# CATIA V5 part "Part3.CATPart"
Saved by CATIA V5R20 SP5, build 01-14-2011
Part number: Part3
Material "DS Light Blue": density 7860 kg/m3, Young's modulus 2e+11 Pa, Poisson ratio 0.266
Bounding box of the stored display mesh (mm): x -36.885 to 36.885, y -32.342 to 32.342, z -80 to 0
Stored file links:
  D:\zhonggao\Part3.CATPart
  C:\Program Files\Dassault Systemes\B20\intel_a\startup\materials\Catalog.CATMaterial
  C:\Program Files\Dassault Systemes\B20\intel_a\startup\materials\blue_env_512x512.jpg
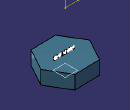
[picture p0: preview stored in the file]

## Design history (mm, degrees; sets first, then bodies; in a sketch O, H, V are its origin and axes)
Body1 (main body), material "DS Light Blue"
  DatumSurface1
  DatumSurface2
  Sketch1 on zx-plane, origin (0, 0, 0), H (-1, 0, 0), V (0, 0, 1)
    polyline C1
    polyline C2
    polyline C3
    polyline C4
    polyline C5
    polyline C6
    polyline C7
    polyline C8
    polyline C9
    polyline C10
    polyline C11
    polyline C12
    polyline C13
    polyline C14
    polyline C15
    polyline C16
    polyline C17
    polyline C18
    polyline C19
    polyline C20
    polyline C21
    polyline C22
    polyline C23
    polyline C24
    polyline C25
  DatumSurface3
  Plane1: type Offset, RefPlane DatumSurface3, Offset 20, reversed
  Sketch2 on Plane1, origin (0, 0, -80), H (1, 0, 0), V (0, 1, 0)
    point P1 (36.8845, 0.7984)
    point P2 (17.7508, 32.3422)
    point P3 (-19.1337, 31.5437)
    point P4 (-36.8845, -0.7984)
    point P5 (-17.7508, -32.3422)
    point P6 (19.1337, -31.5437)
    point P7 (27.3177, 16.5703)
    line L1 (36.8845, 0.7984) -> (17.7508, 32.3422)
    line L2 (17.7508, 32.3422) -> (-19.1337, 31.5437)
    line L3 (-19.1337, 31.5437) -> (-36.8845, -0.7984)
    line L4 (-36.8845, -0.7984) -> (-17.7508, -32.3422)
    line L5 (-17.7508, -32.3422) -> (19.1337, -31.5437)
    line L6 (19.1337, -31.5437) -> (36.8845, 0.7984)
    construction line L7 (0, 0) -> (27.3177, 16.5703)
    construction circle A1 centre (0, 0) radius 36.8932
    construction arc A2 centre (-17.7508, -32.3422) radius 36.8932 from (-36.8845, -0.7984) to (19.1337, -31.5437) cw
    construction arc A3 centre (17.7508, 32.3422) radius 36.8932 from (-19.1337, 31.5437) to (36.8845, 0.7984) ccw
    coincidence: A1 P1, A1 P2, A1 P3, A1 P4, A1 P5, A1 P6, A2 O, A3 O
    midpoint: P7 L1
    parallelism: L1 L4
  Pad1: profile Sketch2, direction (0, 0, 1), length 20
